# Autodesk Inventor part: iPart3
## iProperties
Created: 2005-03
Part Number: iPart3
Document SubType Name: Modeling
Designer: CADCIM
Manufacturer: Standard
Standards Organization: Custom
Author: CADCIM
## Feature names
1. Extrusion1
